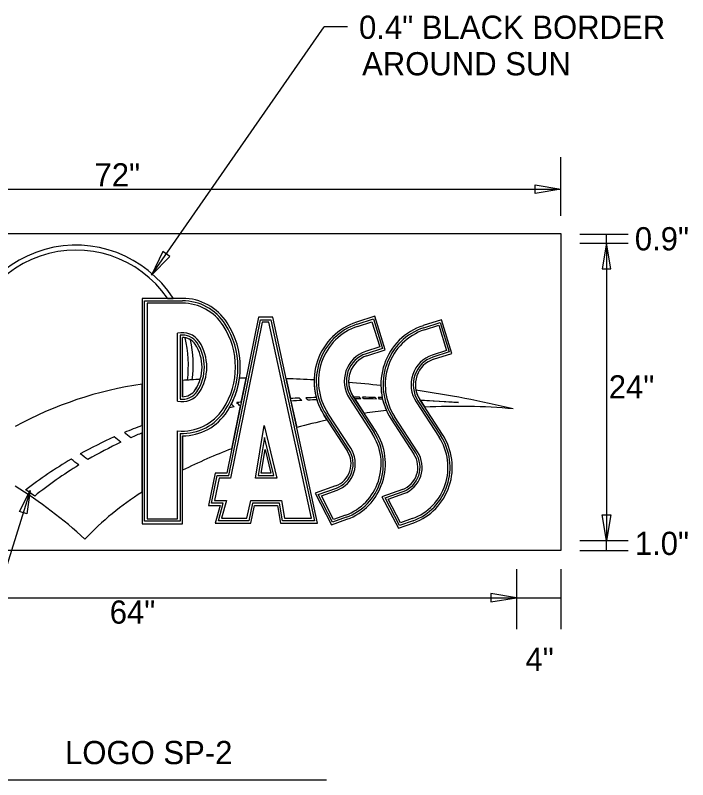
# Model space of a CAD drawing. Extents: x 10268197 to 10268738, y 2141503 to 2142677.
# Drawn here: x 10268684.28 to 10268704.55, y 2142399.46 to 2142422.52 of the extents above; entities that cross this region are included whole.
import ezdxf

# ---------------------------------------------------------------- set-up
doc = ezdxf.new("R2010")
doc.units = 0
for name, color, linetype in [('1', 7, 'Continuous'), ('Default', 7, 'Continuous'), ('GSDims', 7, 'Continuous'), ('TextMisc', 7, 'Continuous')]:
    doc.layers.add(name, color=color, linetype=linetype)

msp = doc.modelspace()

# ---------------------------------------------------------------- linework, layer by layer
at = {"layer": '1'}
for p, q in [((10268688.389, 2142414.678), (10268693.595, 2142422.165)), ((10268694.298, 2142422.165), (10268693.595, 2142422.165)), ((10268690.716, 2142408.631), (10268691.667, 2142413.331)), ((10268691.667, 2142413.331), (10268691.98, 2142413.331)), ((10268691.98, 2142413.331), (10268693.303, 2142407.271)), ((10268690.959, 2142410.832), (10268691.059, 2142410.733)), ((10268691.794, 2142409.785), (10268691.606, 2142408.631)), ((10268692.075, 2142408.631), (10268691.794, 2142409.785)), ((10268690.198, 2142407.803), (10268690.369, 2142408.631)), ((10268690.369, 2142408.631), (10268690.716, 2142408.631)), ((10268691.606, 2142408.631), (10268692.075, 2142408.631)), ((10268691.981, 2142408.705), (10268691.693, 2142408.705)), ((10268684.729, 2142408.184), (10268682.878, 2142402.256)), ((10268690.107, 2142407.73), (10268690.453, 2142407.73)), ((10268690.55, 2142407.803), (10268690.198, 2142407.803)), ((10268690.406, 2142407.271), (10268690.55, 2142407.803)), ((10268691.432, 2142407.803), (10268691.316, 2142407.271)), ((10268692.246, 2142407.803), (10268691.432, 2142407.803)), ((10268692.333, 2142407.271), (10268692.246, 2142407.803)), ((10268691.316, 2142407.271), (10268690.406, 2142407.271)), ((10268693.303, 2142407.271), (10268692.333, 2142407.271)), ((10268700.725, 2142406.37), (10268674.779, 2142406.37))]:
    msp.add_line(p, q, dxfattribs=at)
for points in [[(10268690.453, 2142407.73), (10268690.309, 2142407.198), (10268691.376, 2142407.198), (10268691.491, 2142407.73), (10268692.183, 2142407.73), (10268692.27, 2142407.198), (10268693.394, 2142407.198), (10268692.039, 2142413.405), (10268691.607, 2142413.405), (10268690.655, 2142408.705), (10268690.309, 2142408.705), (10268690.107, 2142407.73)], [(10268690.775, 2142410.807), (10268690.88, 2142410.704), (10268690.738, 2142410.68)], [(10268691.693, 2142408.705), (10268691.808, 2142409.414), (10268691.981, 2142408.705)]]:
    msp.add_lwpolyline(points, dxfattribs=at)
at = {"layer": 'Default'}
for p, q in [((10268688.179, 2142407.254), (10268688.179, 2142413.904)), ((10268688.179, 2142413.904), (10268689.318, 2142413.904)), ((10268688.869, 2142413.978), (10268689.044, 2142413.978)), ((10268688.251, 2142413.831), (10268688.251, 2142407.328)), ((10268689.318, 2142413.831), (10268688.251, 2142413.831)), ((10268688.251, 2142413.831), (10268688.251, 2142407.328)), ((10268689.318, 2142413.831), (10268688.251, 2142413.831)), ((10268691.724, 2142413.257), (10268690.772, 2142408.557)), ((10268691.724, 2142413.257), (10268690.772, 2142408.557)), ((10268691.924, 2142413.257), (10268691.724, 2142413.257)), ((10268691.924, 2142413.257), (10268691.724, 2142413.257)), ((10268693.214, 2142407.345), (10268691.924, 2142413.257)), ((10268693.214, 2142407.345), (10268691.924, 2142413.257)), ((10268694.581, 2142413.195), (10268695.074, 2142413.355)), ((10268694.6, 2142413.132), (10268695.031, 2142413.272)), ((10268694.6, 2142413.132), (10268695.031, 2142413.272)), ((10268695.031, 2142413.272), (10268695.266, 2142412.511)), ((10268695.031, 2142413.272), (10268695.266, 2142412.511)), ((10268695.074, 2142413.355), (10268695.347, 2142412.467)), ((10268696.595, 2142413.09), (10268697.088, 2142413.25)), ((10268697.088, 2142413.25), (10268697.361, 2142412.362)), ((10268696.614, 2142413.027), (10268697.045, 2142413.167)), ((10268696.614, 2142413.027), (10268697.045, 2142413.167)), ((10268697.045, 2142413.167), (10268697.28, 2142412.406)), ((10268697.045, 2142413.167), (10268697.28, 2142412.406)), ((10268689.174, 2142410.88), (10268689.174, 2142412.927)), ((10268689.174, 2142410.88), (10268689.174, 2142412.927)), ((10268689.246, 2142412.864), (10268689.246, 2142410.942)), ((10268689.318, 2142411.01), (10268689.318, 2142412.796)), ((10268695.266, 2142412.511), (10268694.835, 2142412.371)), ((10268695.266, 2142412.511), (10268694.835, 2142412.371)), ((10268695.347, 2142412.467), (10268694.854, 2142412.308)), ((10268697.28, 2142412.406), (10268696.848, 2142412.266)), ((10268697.28, 2142412.406), (10268696.848, 2142412.266)), ((10268697.361, 2142412.362), (10268696.868, 2142412.203)), ((10268688.107, 2142410.14), (10268688.107, 2142411.39)), ((10268689.318, 2142411.503), (10268689.318, 2142411.01)), ((10268691.089, 2142410.847), (10268691.235, 2142411.568)), ((10268692.443, 2142411.553), (10268692.574, 2142410.956)), ((10268689.704, 2142411.215), (10268689.704, 2142411.215)), ((10268694.35, 2142410.959), (10268695.04, 2142409.898)), ((10268694.35, 2142410.959), (10268695.04, 2142409.898)), ((10268694.404, 2142410.996), (10268695.094, 2142409.934)), ((10268695.148, 2142409.971), (10268694.458, 2142411.033)), ((10268694.458, 2142411.033), (10268694.481, 2142410.997)), ((10268694.516, 2142410.944), (10268694.8, 2142410.507)), ((10268696.418, 2142410.891), (10268697.108, 2142409.829)), ((10268697.162, 2142409.866), (10268696.472, 2142410.928)), ((10268696.472, 2142410.928), (10268696.478, 2142410.919)), ((10268696.478, 2142410.919), (10268697.638, 2142410.833)), ((10268697.638, 2142410.833), (10268696.493, 2142410.894)), ((10268696.493, 2142410.894), (10268696.624, 2142410.693)), ((10268690.804, 2142409.442), (10268691.065, 2142410.731)), ((10268692.59, 2142410.88), (10268692.765, 2142410.082)), ((10268696.364, 2142410.854), (10268697.054, 2142409.793)), ((10268696.364, 2142410.854), (10268697.054, 2142409.793)), ((10268690.671, 2142410.569), (10268690.671, 2142410.569)), ((10268693.594, 2142410.443), (10268694.285, 2142409.381)), ((10268693.685, 2142410.303), (10268693.594, 2142410.443)), ((10268694.339, 2142409.418), (10268693.648, 2142410.479)), ((10268694.392, 2142409.455), (10268693.702, 2142410.516)), ((10268694.392, 2142409.455), (10268693.702, 2142410.516)), ((10268695.608, 2142410.338), (10268696.298, 2142409.276)), ((10268696.352, 2142409.313), (10268695.662, 2142410.375)), ((10268696.406, 2142409.35), (10268695.716, 2142410.411)), ((10268696.406, 2142409.35), (10268695.716, 2142410.411)), ((10268689.174, 2142407.328), (10268689.174, 2142409.983)), ((10268689.174, 2142407.328), (10268689.174, 2142409.983)), ((10268691.523, 2142408.557), (10268691.78, 2142410.14)), ((10268691.523, 2142408.557), (10268691.78, 2142410.14)), ((10268691.78, 2142410.14), (10268692.166, 2142408.557)), ((10268691.78, 2142410.14), (10268692.166, 2142408.557)), ((10268688.107, 2142408.134), (10268688.107, 2142409.92)), ((10268689.246, 2142409.904), (10268689.246, 2142407.254)), ((10268689.318, 2142409.828), (10268689.318, 2142408.791)), ((10268690.426, 2142408.557), (10268690.285, 2142407.877)), ((10268690.426, 2142408.557), (10268690.285, 2142407.877)), ((10268690.772, 2142408.557), (10268690.426, 2142408.557)), ((10268690.772, 2142408.557), (10268690.426, 2142408.557)), ((10268692.166, 2142408.557), (10268691.523, 2142408.557)), ((10268692.166, 2142408.557), (10268691.523, 2142408.557)), ((10268684.865, 2142408.015), (10268684.594, 2142408.197)), ((10268693.413, 2142408.061), (10268693.958, 2142408.255)), ((10268693.506, 2142408.024), (10268693.979, 2142408.193)), ((10268693.506, 2142408.024), (10268693.979, 2142408.193)), ((10268695.427, 2142407.956), (10268695.971, 2142408.15)), ((10268693.846, 2142407.23), (10268693.413, 2142408.061)), ((10268693.877, 2142407.311), (10268693.506, 2142408.024)), ((10268693.877, 2142407.311), (10268693.506, 2142408.024)), ((10268695.859, 2142407.125), (10268695.427, 2142407.956)), ((10268695.52, 2142407.919), (10268695.993, 2142408.088)), ((10268695.52, 2142407.919), (10268695.993, 2142408.088)), ((10268695.891, 2142407.206), (10268695.52, 2142407.919)), ((10268695.891, 2142407.206), (10268695.52, 2142407.919)), ((10268690.285, 2142407.877), (10268690.643, 2142407.877)), ((10268690.285, 2142407.877), (10268690.643, 2142407.877)), ((10268690.643, 2142407.877), (10268690.499, 2142407.345)), ((10268690.643, 2142407.877), (10268690.499, 2142407.345)), ((10268691.26, 2142407.345), (10268691.376, 2142407.877)), ((10268691.26, 2142407.345), (10268691.376, 2142407.877)), ((10268691.376, 2142407.877), (10268692.305, 2142407.877)), ((10268691.376, 2142407.877), (10268692.305, 2142407.877)), ((10268692.305, 2142407.877), (10268692.392, 2142407.345)), ((10268692.305, 2142407.877), (10268692.392, 2142407.345)), ((10268694.235, 2142407.439), (10268693.877, 2142407.311)), ((10268694.235, 2142407.439), (10268693.877, 2142407.311)), ((10268689.246, 2142407.254), (10268688.179, 2142407.254)), ((10268688.251, 2142407.328), (10268689.174, 2142407.328)), ((10268688.251, 2142407.328), (10268689.174, 2142407.328)), ((10268690.499, 2142407.345), (10268691.26, 2142407.345)), ((10268690.499, 2142407.345), (10268691.26, 2142407.345)), ((10268692.392, 2142407.345), (10268693.214, 2142407.345)), ((10268692.392, 2142407.345), (10268693.214, 2142407.345)), ((10268694.256, 2142407.376), (10268693.846, 2142407.23)), ((10268696.27, 2142407.271), (10268695.859, 2142407.125)), ((10268696.248, 2142407.334), (10268695.891, 2142407.206)), ((10268696.248, 2142407.334), (10268695.891, 2142407.206)), ((10268700.725, 2142406.37), (10268674.779, 2142406.37)), ((10268683.234, 2142399.458), (10268693.665, 2142399.458))]:
    msp.add_line(p, q, dxfattribs=at)
for points in [[(10268674.779, 2142406.37), (10268674.779, 2142415.938), (10268700.725, 2142415.938), (10268700.725, 2142406.37)], [(10268689.318, 2142413.978), (10268688.107, 2142413.978), (10268688.107, 2142407.18), (10268689.318, 2142407.18), (10268689.318, 2142409.828)], [(10268694.874, 2142412.244), (10268695.429, 2142412.424), (10268695.116, 2142413.438), (10268694.561, 2142413.259)], [(10268690.611, 2142413.196), (10268690.611, 2142413.196)], [(10268696.888, 2142412.139), (10268697.442, 2142412.319), (10268697.13, 2142413.333), (10268696.575, 2142413.154)], [(10268689.764, 2142412.633), (10268689.764, 2142412.634)], [(10268689.704, 2142411.215), (10268689.704, 2142411.215)], [(10268689.764, 2142411.172), (10268689.764, 2142411.173)], [(10268690.796, 2142410.787), (10268690.88, 2142410.704), (10268690.738, 2142410.68)], [(10268691.065, 2142410.731), (10268691.059, 2142410.733)], [(10268690.611, 2142410.61), (10268690.611, 2142410.61)], [(10268690.671, 2142410.569), (10268690.671, 2142410.569)], [(10268693.936, 2142408.318), (10268693.32, 2142408.099), (10268693.814, 2142407.148), (10268694.277, 2142407.313)], [(10268695.95, 2142408.213), (10268695.334, 2142407.994), (10268695.828, 2142407.043), (10268696.291, 2142407.208)]]:
    msp.add_lwpolyline(points, dxfattribs=at)
for centre, major_axis, ratio, start_param, end_param in [((10268686.111, 2142411.962), (0, 3.62), 0.97582, 5.303349, 7.802858), ((10268686.111, 2142411.962), (0, 3.62), 0.97582, 5.303349, 7.802858), ((10268686.111, 2142411.962), (0, 3.472), 0.97582, 5.332201, 7.884008), ((10268686.111, 2142411.962), (0, 3.472), 0.97582, 5.332201, 7.884008), ((10268689.322, 2142412.318), (0, 1.66), 0.97582, 5.298823, 6.285263), ((10268689.322, 2142412.318), (0, 1.586), 0.97582, 5.29886, 6.285263), ((10268689.318, 2142412.346), (0, 1.485), 0.990269, 5.289759, 6.283185), ((10268689.318, 2142412.346), (0, 1.485), 0.990269, 5.289759, 6.283185), ((10268689.322, 2142412.318), (0, 1.586), 0.97582, 5.298823, 5.29886), ((10268688.704, 2142411.903), (0, 2.343), 0.97582, 4.127723, 5.297054), ((10268688.704, 2142411.903), (0, 2.343), 0.97582, 5.297054, 5.297084), ((10268688.704, 2142411.903), (0, 2.417), 0.97582, 4.127694, 5.297084), ((10268695.11, 2142411.478), (0, 1.867), 0.97582, 0.306207, 2.15869), ((10268695.11, 2142411.478), (0, 1.801), 0.97582, 0.306207, 2.15869), ((10268689.318, 2142412.346), (0.605, 0), 0.987937, 0.57737, 1.811353), ((10268689.318, 2142412.346), (0.605, 0), 0.987937, 0.57737, 1.811353), ((10268688.646, 2142411.903), (0, 2.296), 0.989796, 4.135019, 5.289759), ((10268688.646, 2142411.903), (0, 2.296), 0.989796, 4.135019, 5.289759), ((10268695.11, 2142411.478), (0, 1.734), 0.975477, 0.305879, 2.158799), ((10268695.11, 2142411.478), (0, 1.734), 0.975477, 0.305879, 2.158799), ((10268697.124, 2142411.373), (0, 1.867), 0.97582, 0.306207, 2.15869), ((10268697.124, 2142411.373), (0, 1.801), 0.97582, 0.306207, 2.15869), ((10268697.123, 2142411.373), (0, 1.734), 0.975477, 0.305879, 2.158799), ((10268697.123, 2142411.373), (0, 1.734), 0.975477, 0.305879, 2.158799), ((10268689.322, 2142412.318), (0, 0.552), 0.97582, 5.321397, 6.424928), ((10268689.322, 2142412.318), (0, 0.478), 0.97582, 5.321397, 6.29161), ((10268686.111, 2142411.962), (0, 3.472), 0.97582, 4.58247, 4.952925), ((10268689.318, 2142412.346), (0.461, 0), 0.976302, 1.01124, 1.389925), ((10268686.111, 2142411.962), (0, 3.472), 0.97582, 4.58247, 4.952925), ((10268686.111, 2142411.962), (0, 3.62), 0.97582, 4.590045, 4.925551), ((10268686.111, 2142411.962), (0, 3.62), 0.97582, 4.590045, 4.925551), ((10268688.705, 2142411.903), (0, 1.234), 0.97582, 4.120664, 5.304114), ((10268688.705, 2142411.903), (0, 1.308), 0.97582, 4.120664, 5.304114), ((10268688.646, 2142411.903), (0, 1.409), 0.998806, 4.135019, 5.289759), ((10268688.646, 2142411.903), (0, 1.409), 0.998806, 4.135019, 5.289759), ((10268695.11, 2142411.478), (0, 0.936), 0.975477, 0.305879, 2.158799), ((10268695.11, 2142411.478), (0, 0.936), 0.975477, 0.305879, 2.158799), ((10268695.11, 2142411.478), (0, 0.87), 0.97582, 0.306207, 2.15869), ((10268695.11, 2142411.478), (0, 0.803), 0.97582, 0.306207, 2.15869), ((10268697.123, 2142411.373), (0, 0.936), 0.975477, 0.305879, 2.158799), ((10268697.123, 2142411.373), (0, 0.936), 0.975477, 0.305879, 2.158799), ((10268697.124, 2142411.373), (0, 0.87), 0.97582, 0.306207, 2.15869), ((10268697.124, 2142411.373), (0, 0.803), 0.97582, 0.306207, 2.15869), ((10268689.687, 2142399.778), (0, 11.724), 0.97582, 0.138501, 0.492135), ((10268689.687, 2142399.778), (0, 11.724), 0.97582, 0.138501, 0.492135), ((10268691.424, 2142376.833), (0, -34.735), 0.98893, 3.187344, 3.202947), ((10268691.424, 2142376.833), (0, -34.735), 0.98893, 3.187344, 3.202947), ((10268691.424, 2142376.833), (0, -34.735), 0.98893, 3.194251, 3.198517), ((10268688.705, 2142411.903), (0, 1.234), 0.97582, 4.120664, 4.406744), ((10268688.704, 2142411.903), (0, 2.417), 0.97582, 4.232077, 4.572378), ((10268691.424, 2142376.833), (0, -34.735), 0.98893, 3.147118, 3.152801), ((10268691.424, 2142376.833), (0, -34.735), 0.98893, 3.147118, 3.152801), ((10268691.424, 2142376.833), (0, -34.735), 0.98893, 3.087298, 3.111926), ((10268691.424, 2142376.833), (0, -34.735), 0.98893, 3.087298, 3.111926), ((10268695.11, 2142411.478), (0, 1.867), 0.97582, 1.5501, 1.838244), ((10268691.424, 2142376.833), (0, -34.735), 0.98893, 3.028464, 3.056997), ((10268691.424, 2142376.833), (0, -34.735), 0.98893, 3.028464, 3.056997), ((10268695.11, 2142411.478), (0, 0.803), 0.97582, 1.61365, 2.15869), ((10268689.318, 2142411.46), (0.605, 0), 0.987937, 4.471833, 5.705815), ((10268689.318, 2142411.46), (0.605, 0), 0.987937, 4.471833, 5.705815), ((10268689.322, 2142411.489), (0, 0.553), 0.97582, 3.001239, 4.102113), ((10268689.322, 2142411.489), (0, 0.479), 0.97582, 3.134436, 4.102113), ((10268689.322, 2142411.489), (0, 0.479), 0.97582, 3.134436, 4.102113), ((10268697.124, 2142411.373), (0, 1.867), 0.97582, 1.58538, 1.781939), ((10268691.424, 2142376.833), (0, -34.735), 0.98893, 2.910551, 2.997508), ((10268691.424, 2142376.833), (0, -34.735), 0.98893, 2.910551, 2.997508), ((10268697.124, 2142411.373), (0, 0.803), 0.97582, 1.777902, 2.15869), ((10268694.297, 2142374.433), (0, -36.564), 0.988257, 3.181604, 3.189295), ((10268694.732, 2142374.38), (0, -36.564), 0.988257, 3.191919, 3.200901), ((10268676.598, 2142395.741), (0, 22.461), 0.984327, 5.453123, 5.457325), ((10268694.297, 2142374.433), (0, -36.564), 0.988257, 3.167715, 3.176345), ((10268676.598, 2142395.741), (0, 22.609), 0.98427, 5.447702, 5.451744), ((10268694.732, 2142374.38), (0, -36.564), 0.988257, 3.179241, 3.186723), ((10268695.11, 2142411.478), (0, 1.867), 0.97582, 1.875041, 2.15869), ((10268694.297, 2142374.433), (0, -36.564), 0.988257, 3.131695, 3.136489), ((10268694.732, 2142374.38), (0, -36.564), 0.988257, 3.142595, 3.147585), ((10268676.598, 2142395.741), (0, 23.865), 0.983807, 5.403078, 5.405838), ((10268694.297, 2142374.433), (0, -36.564), 0.988257, 3.118574, 3.129071), ((10268676.598, 2142395.741), (0, 23.939), 0.983781, 5.400528, 5.403217), ((10268694.732, 2142374.38), (0, -36.564), 0.988257, 3.129621, 3.14), ((10268676.598, 2142395.741), (0, 24.234), 0.98368, 5.390405, 5.392813), ((10268676.598, 2142395.741), (0, 24.308), 0.983655, 5.387892, 5.390232), ((10268694.297, 2142374.433), (0, -36.564), 0.988257, 3.112651, 3.11595), ((10268694.732, 2142374.38), (0, -36.564), 0.988257, 3.124437, 3.127026), ((10268697.124, 2142411.373), (0, 1.867), 0.97582, 1.805305, 2.000126), ((10268688.704, 2142411.903), (0, 2.417), 0.97582, 4.127694, 4.181576), ((10268692.571, 2142397.624), (0, -13.308), 0.987081, 3.2547, 3.264672), ((10268676.598, 2142395.741), (0, 20.983), 0.984951, 5.508238, 5.514999), ((10268697.619, 2142390.98), (0, 19.74), 0.975477, 6.196281, 6.334881), ((10268697.619, 2142390.98), (0, 19.74), 0.975477, 6.196281, 6.334881), ((10268689.318, 2142411.46), (0, 1.485), 0.990269, 3.043371, 4.135019), ((10268689.318, 2142411.46), (0, 1.485), 0.990269, 3.043371, 4.135019), ((10268689.322, 2142411.488), (0, 1.586), 0.97582, 3.092812, 4.125918), ((10268689.322, 2142411.488), (0, 1.66), 0.97582, 3.139515, 4.125955), ((10268689.322, 2142411.488), (0, 1.66), 0.97582, 3.139515, 4.125955), ((10268689.322, 2142411.488), (0, 1.586), 0.97582, 4.125918, 4.125955), ((10268688.704, 2142411.903), (0, 2.343), 0.97582, 4.127694, 4.127723), ((10268697.619, 2142390.98), (0, 19.74), 0.975477, 0.111981, 0.146944), ((10268697.619, 2142390.98), (0, 19.74), 0.975477, 0.111981, 0.146944), ((10268697.619, 2142390.98), (0, 19.74), 0.975477, 0.20577, 0.254866), ((10268697.619, 2142390.98), (0, 19.74), 0.975477, 0.20577, 0.254866), ((10268692.571, 2142397.624), (0, -13.308), 0.987081, 3.48834, 3.532255), ((10268693.708, 2142408.988), (0, 1.773), 0.97582, 3.476656, 5.300276), ((10268692.571, 2142397.624), (0, -13.308), 0.987081, 3.557551, 3.644446), ((10268676.598, 2142395.741), (0, 17.732), 0.986688, 5.613012, 5.627647), ((10268676.598, 2142395.741), (0, 18.027), 0.986504, 5.604488, 5.618403), ((10268693.007, 2142397.572), (0, -13.308), 0.987081, 3.5238, 3.552221), ((10268693.709, 2142408.988), (0, -1.64), 0.975477, 0.334737, 2.158799), ((10268693.709, 2142408.988), (0, -1.64), 0.975477, 0.334737, 2.158799), ((10268693.708, 2142408.988), (0, 1.707), 0.97582, 3.476656, 5.300276), ((10268695.723, 2142408.883), (0, -1.64), 0.975477, 0.334737, 2.158799), ((10268695.723, 2142408.883), (0, -1.64), 0.975477, 0.334737, 2.158799), ((10268695.722, 2142408.883), (0, 1.707), 0.97582, 3.476656, 5.300276), ((10268695.722, 2142408.883), (0, 1.773), 0.97582, 3.476656, 5.300276), ((10268693.007, 2142397.572), (0, -13.308), 0.987081, 3.577057, 3.66248), ((10268676.598, 2142395.741), (0, 16.697), 0.987382, 5.641271, 5.658477), ((10268697.619, 2142390.98), (0, 19.74), 0.975477, 0.36175, 0.445699), ((10268697.619, 2142390.98), (0, 19.74), 0.975477, 0.36175, 0.445699), ((10268693.709, 2142408.988), (0, 0.709), 0.97582, 3.476661, 5.300276), ((10268693.709, 2142408.988), (0, 0.776), 0.97582, 3.476661, 5.300276), ((10268693.709, 2142408.988), (0, -0.842), 0.975477, 0.334742, 2.158799), ((10268693.709, 2142408.988), (0, -0.842), 0.975477, 0.334742, 2.158799), ((10268695.723, 2142408.883), (0, 0.709), 0.97582, 3.476661, 5.300276), ((10268695.723, 2142408.883), (0, 0.776), 0.97582, 3.476661, 5.300276), ((10268695.723, 2142408.883), (0, -0.842), 0.975477, 0.334742, 2.158799), ((10268695.723, 2142408.883), (0, -0.842), 0.975477, 0.334742, 2.158799), ((10268692.571, 2142397.624), (0, -13.308), 0.987081, 3.668845, 3.794286), ((10268676.598, 2142395.741), (0, 16.402), 0.987597, 5.648885, 5.666846), ((10268693.007, 2142397.572), (0, -13.308), 0.987081, 3.686493, 3.810103), ((10268676.659, 2142395.507), (0, 14.998), 0.97582, 5.556667, 5.735414), ((10268676.659, 2142395.507), (0, 14.998), 0.97582, 5.556667, 5.735414), ((10268692.674, 2142400.661), (0, -8.785), 0.98893, 3.695067, 3.951695), ((10268692.674, 2142400.661), (0, -8.785), 0.98893, 3.695067, 3.951695)]:
    msp.add_ellipse(centre, major_axis=major_axis, ratio=ratio, start_param=start_param, end_param=end_param, dxfattribs=at)
at = {"layer": 'GSDims'}
for p, q in [((10268674.779, 2142417.271), (10268700.725, 2142417.271)), ((10268701.295, 2142415.918), (10268702.751, 2142415.918)), ((10268702.099, 2142415.638), (10268702.099, 2142415.918)), ((10268701.295, 2142415.638), (10268702.751, 2142415.638)), ((10268702.099, 2142415.638), (10268702.099, 2142406.672)), ((10268701.295, 2142406.672), (10268702.751, 2142406.672)), ((10268702.099, 2142406.37), (10268702.099, 2142406.672)), ((10268701.295, 2142406.37), (10268702.751, 2142406.37)), ((10268699.386, 2142405.805), (10268699.386, 2142404.002)), ((10268700.725, 2142405.805), (10268700.725, 2142404.002)), ((10268676.151, 2142404.948), (10268699.386, 2142404.948)), ((10268699.386, 2142404.948), (10268700.725, 2142404.948))]:
    msp.add_line(p, q, dxfattribs=at)
for points in [[(10268700.725, 2142417.271), (10268699.951, 2142417.142), (10268699.951, 2142417.4)], [(10268702.099, 2142415.638), (10268701.97, 2142414.864), (10268702.228, 2142414.864)], [(10268688.389, 2142414.678), (10268688.937, 2142415.24), (10268688.725, 2142415.388)], [(10268684.729, 2142408.184), (10268684.631, 2142407.477), (10268684.407, 2142407.547)], [(10268702.099, 2142406.672), (10268701.97, 2142407.447), (10268702.228, 2142407.447)], [(10268699.386, 2142404.948), (10268698.611, 2142405.078), (10268698.611, 2142404.819)]]:
    msp.add_lwpolyline(points, close=True, dxfattribs=at)
at = {"layer": 'TextMisc'}
msp.add_line((10268700.725, 2142416.464), (10268700.725, 2142418.232), dxfattribs=at)

# ---------------------------------------------------------------- texts
at = {"layer": '1'}
for s, p in [('0.4" BLACK BORDER', (10268694.642, 2142421.805)), ('AROUND SUN', (10268694.734, 2142420.704)), ('72"', (10268686.669, 2142417.353)), ('0.9"', (10268702.955, 2142415.425)), ('24"', (10268702.17, 2142410.957)), ('1.0"', (10268702.955, 2142406.237)), ('64"', (10268687.127, 2142404.165)), ('4"', (10268699.659, 2142402.739)), ('LOGO SP-2', (10268685.78, 2142399.927))]:
    msp.add_text(s, height=0.7, dxfattribs=at).set_placement(p)

doc.saveas('drawing.dxf')
